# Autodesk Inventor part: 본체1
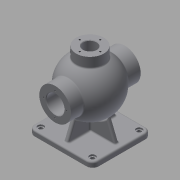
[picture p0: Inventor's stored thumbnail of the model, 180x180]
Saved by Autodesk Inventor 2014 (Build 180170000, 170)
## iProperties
Created: 2015-10
Part Number: 본체1
Material: Generic
Document SubType Name: Modeling
Designer: youjin13
Density: 1 g/cm^3
Appearance: Default
Author: youjin13
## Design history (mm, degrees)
sketch "Sketch1"
  geometry: L1 (50.5, -57.5)-(-50.5, -57.5); L2 (-62.5, -45.5)-(-62.5, 45.5); L3 (-50.5, 57.5)-(50.5, 57.5); L4 (62.5, 45.5)-(62.5, -45.5); L5 (62.5, -57.5)-(-62.5, 57.5); L6 (-62.5, -57.5)-(62.5, 57.5); A1 r 12 centre (-50.5, 45.5) between (-50.5, 57.5) and (-62.5, 45.5); A2 r 12 centre (50.5, 45.5) between (62.5, 45.5) and (50.5, 57.5); A3 r 12 centre (50.5, -45.5) between (50.5, -57.5) and (62.5, -45.5); A4 r 12 centre (-50.5, -45.5) between (-62.5, -45.5) and (-50.5, -57.5); 1 further point
  constraints: 12 end point, 8 point on circle, 8 point on line, 8 tangent, 4 centre point, 3 equal radius, 2 midpoint, 2 parallel, 1 horizontal, 1 perpendicular
  dimensions: "d0" = 125 distance of L5.end L6.end; "d1" = 115 distance of L6.end L5.start; "d2" = 12 radius of A1
extrude "Extrusion1" new body sketch "Sketch1" distance "d3" = 10; taper "d4" = 0 deg
sketch "Sketch2"
  geometry: A1 r 12 centre (-50.5, 45.5) between (-50.5, 57.5) and (-62.5, 45.5) reference; A2 r 12 centre (-50.5, -45.5) between (-62.5, -45.5) and (-50.5, -57.5) reference; A3 r 12 centre (50.5, -45.5) between (50.5, -57.5) and (62.5, -45.5) reference; A4 r 12 centre (50.5, 45.5) between (62.5, 45.5) and (50.5, 57.5) reference; 5 further points
  constraints: 4 coincident
hole "Hole1" sketch "Sketch2" at (-50.5, 45.5), (50.5, 45.5), (50.5, -45.5), (-50.5, -45.5) diameter "d5" = 8; stored, may be unused: countersink angle "d9" = 90 deg, drill point angle "d11" = 0 deg; dims "d6" = 6, "d7" = 12, "d8" = 3, "d10" = 8
sketch "Sketch3"
  geometry: L1 (50.5, 0)-(-50.5, 0) reference; L2 (0, 138)-(0, 32); A1 r 53 centre (0, 85) between (0, 32) and (0, 138); 3 further points
  constraints: 2 end point, 2 midpoint, 2 point on circle, 1 centre point, 1 coincident, 1 perpendicular, 1 vertical alignment
  dimensions: "d14" = 53 radius of A1; "d15" = 85 distance of point (0, 0) A1.centre
revolve "Revolution1" sketch "Sketch3" stored, may be unused: angle "d16" = 90 deg
workplane "Work Plane1"
sketch "Sketch4"
  geometry: C1 r 31 at (0, 85); 1 further point
  constraints: 1 centre point, 1 vertical alignment
  dimensions: "d18" = 62 diameter of C1; "d19" = 85 distance of point (0, 0) C1.centre
extrude "Extrusion2" join sketch "Sketch4" stored distance "d20" = 85 (= d19); taper "d21" = 0 deg
mirror "Mirror1"
sketch "Sketch5"
  geometry: L1 (0, 128)-(0, 42); C1 r 53 at (0, 85) reference; A1 r 43 centre (0, 85) between (0, 128) and (0, 42); 2 further points
  constraints: 2 coincident, 2 end point, 2 point on circle, 1 centre point, 1 midpoint, 1 vertical
  dimensions: "d22" = 86 diameter of A1
revolve "Revolution2" sketch "Sketch5" stored, may be unused: angle "d23" = 90 deg
sketch "Sketch6"
  geometry: C1 r 31 at (0, 0) reference; C2 r 17.5 at (0, 0); 1 further point
  constraints: 1 centre point, 1 coincident
  dimensions: "d24" = 35 diameter of C2
extrude "Extrusion3" cut sketch "Sketch6" distance "d25" = 16; taper "d26" = 0 deg
sketch "Sketch7"
  geometry: C1 r 17.5 at (0, 0) reference; C2 r 18.5 at (0, 0); 1 further point
  constraints: 1 centre point, 1 coincident
  dimensions: "d27" = 37 diameter of C2
extrude "Extrusion4" cut sketch "Sketch7" distance "d28" = 1.75; taper "d29" = 0 deg
sketch "Sketch8"
  geometry: C1 r 31 at (0, 0) reference; C2 r 17.5 at (0, 0); 1 further point
  constraints: 1 centre point, 1 coincident
  dimensions: "d30" = 35 diameter of C2
extrude "Extrusion5" cut sketch "Sketch8" stored distance "d31" = 1.75; taper "d32" = 0 deg
workplane "Work Plane2"
sketch "Sketch11"
  geometry: C1 r 27 at (0, 0); 1 further point
  constraints: 1 centre point, 1 coincident
  dimensions: "d47" = 54 diameter of C1
extrude "Extrusion8" join sketch "Sketch11" stored distance "d48" = 8; taper "d49" = 0 deg
sketch "Sketch12"
  geometry: C1 r 27 at (0, 0) reference; C2 r 13 at (0, 0)
  constraints: 1 centre point, 1 coincident
  dimensions: "d50" = 26 diameter of C2
extrude "Extrusion9" cut sketch "Sketch12" stored distance "d51" = 8; taper "d52" = 0 deg
chamfer "Chamfer1" distance "d53" = 1; stored, may be unused: second distance "d54" = 2, angle "d55" = 45 deg
sketch "Sketch13"
  geometry: C1 r 31 at (0, 0) reference; C2 r 18.5 at (0, 0) reference; A1 r 22.5 centre (0, 0) between (0, 22.5) and (-22.5, 0); 3 further points
  constraints: 4 point on circle, 2 horizontal alignment, 2 vertical alignment, 1 centre point, 1 coincident
  dimensions: "d56" = 45 diameter of A1
hole "Hole2" sketch "Sketch13" at (0, 22.5), (0, -22.5), (22.5, 0), (-22.5, 0) diameter "d57" = 3.242; stored, may be unused: countersink angle "d61" = 90 deg, drill point angle "d63" = 118 deg; dims "d58" = 12, "d59" = 12, "d60" = 3, "d62" = 15
sketch "Sketch14"
  geometry: C1 r 31 at (0, 0) reference; C2 r 18.5 at (0, 0) reference; A1 r 24 centre (0, 0) between (0, 24) and (24, 0); 3 further points
  constraints: 4 point on circle, 2 horizontal alignment, 2 vertical alignment, 1 centre point, 1 coincident
  dimensions: "d64" = 48 diameter of A1
hole "Hole3" sketch "Sketch14" at (0, -24), (0, 24), (24, 0), (-24, 0) diameter "d65" = 3.242; stored, may be unused: countersink angle "d69" = 90 deg, drill point angle "d71" = 118 deg; dims "d66" = 16, "d67" = 12, "d68" = 3, "d70" = 19
sketch "Sketch15"
  geometry: C1 r 27 at (0, 0) reference; C2 r 14 at (0, 0) reference; A1 r 20 centre (0, 0) between (0, 20) and (20, 0); 2 further points
  constraints: 4 point on circle, 2 horizontal alignment, 2 vertical alignment, 1 centre point, 1 coincident
  dimensions: "d72" = 40 diameter of A1
hole "Hole4" sketch "Sketch15" at (0, 20), (0, -20), (-20, 0), (20, 0) diameter "d73" = 3.242; stored, may be unused: countersink angle "d77" = 90 deg, drill point angle "d79" = 118 deg; dims "d74" = 9, "d75" = 12, "d76" = 3, "d78" = 11
workplane "Work Plane3"
sketch "Sketch16"
  geometry: L1 (-27, 150)-(27, 150) reference; 2 further points
  constraints: 1 vertical alignment, 1 other
  dimensions: "d81" = 10 distance from line of point (0, 140) L1
emboss "Emboss1" sketch "Sketch16" dims "d0" = 125, "d1" = 115, "d2" = 12, "d5" = 8, "d7" = 12, "d8" = 3, "d10" = 8, "d21" = 0, "d62" = 15, "d82" = 0.5, "d83" = 0, "d111" = 22 deg
sketch "Sketch19"
  geometry: L1 (-57.5, 0)-(-57.5, 10) reference; L2 (45.5, 10)-(-45.5, 10) reference; L3 (-51.5, 10)-(-39.5, 10) reference; L4 (-45.5, 10)-(-57.5, 10) reference; L5 (39.5, 10)-(51.5, 10) reference; L6 (57.5, 10)-(45.5, 10) reference; L7 (57.5, 0)-(57.5, 10) reference; L8 (-33.719, 44.109)-(-47.5, 10); L9 (33.719, 44.109)-(47.5, 10); A1 r 53 centre (0, 85) between (42.988, 116) and (42.988, 54) reference; 1 further point
  constraints: 4 end point, 2 point on circle, 2 point on line
  dimensions: "d104" = 10 distance of L1.end L8.end; "d105" = 22 deg angle of L8 L1; "d106" = 22 deg angle of L7 L9; "d107" = 10 distance of L6.start L9.end
extrude "Extrusion10" join sketch "Sketch19" stored distance "d108" = 8; taper "d109" = 0 deg
sketch "Sketch20"
  geometry: L1 (-62.5, 0)-(-62.5, 10) reference; L2 (-56.5, 10)-(-44.5, 10) reference; L3 (-50.5, 10)-(-62.5, 10) reference; L4 (50.5, 10)-(-50.5, 10) reference; L5 (44.5, 10)-(56.5, 10) reference; L6 (-52.5, 10)-(-37.379, 47.426); L7 (37.379, 47.426)-(52.5, 10); L8 (62.5, 0)-(62.5, 10) reference; A1 r 53 centre (0, 85) between (-27, 130.607) and (27, 130.607) reference; 1 further point
  constraints: 4 end point, 2 point on circle, 2 point on line
  dimensions: "d111" = 22 deg angle of L1 L6; "d112" = 22 deg angle of L8 L7; "d113" = 10 distance of L8.end L7.end; "d114" = 10 distance from line of L1 L6.start
extrude "Extrusion11" join sketch "Sketch20" stored distance "d115" = 8; taper "d116" = 0 deg
fillet "Fillet2" dims "d117" = 3
fillet "Fillet3" dims "d118" = 3
fillet "Fillet4" dims "d119" = 3
fillet "Fillet5" dims "d120" = 3
body "Solid1"
other parameters: "d17" = -68, "d80" = -27.5
